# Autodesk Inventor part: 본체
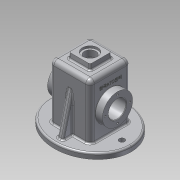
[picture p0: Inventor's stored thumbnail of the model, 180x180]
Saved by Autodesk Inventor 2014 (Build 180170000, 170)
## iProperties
Created: 2017-07
Part Number: 본체
Material: 알루미늄 6061
Document SubType Name: Modeling
Designer: user
Density: 2.71 g/cm^3
Appearance: 알루미늄 - 평지
Mass: 892.712 g
Surface Area: 987.354 cm^2
Volume: 329.414 cm^3
Author: user
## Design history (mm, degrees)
sketch "스케치1"
  geometry: 1 further point
sketch "스케치2"
  geometry: 1 further point
sketch "스케치3"
  geometry: 1 further point; 1 other entity
  constraints: 2 other
extrude "돌출1" new body sketch "스케치3" distance "d2" = 10; taper "d3" = 0 deg
sketch "스케치4"
  geometry: L1 (-37, -37)-(37, -37); L2 (37, -37)-(37, 37); L3 (37, 37)-(-37, 37); L4 (-37, 37)-(-37, -37); L5 (-37, -37)-(37, 37); L6 (37, -37)-(-37, 37); 1 further point; 1 other entity
  constraints: 12 end point, 2 midpoint, 2 parallel, 1 horizontal, 1 perpendicular, 1 other
  dimensions: "d4" = 74 distance of L3.end L2.end; "d5" = 74 distance of L2.end L1.end
extrude "돌출2" join sketch "스케치4" distance "d6" = 100; taper "d7" = 0 deg
fillet "모깎기1" dims "d8" = 8
fillet "모깎기2" dims "d9" = 8
sketch "스케치5"
  geometry: L1 (-32, -32)-(32, -32); L2 (32, -32)-(32, 32); L3 (32, 32)-(-32, 32); L4 (-32, 32)-(-32, -32); L5 (-32, -32)-(32, 32); L6 (32, -32)-(-32, 32); 1 further point; 1 other entity
  constraints: 12 end point, 2 midpoint, 2 parallel, 1 horizontal, 1 perpendicular, 1 other
  dimensions: "d10" = 64 distance of L3.end L2.end; "d11" = 64 distance of L2.end L1.end
extrude "돌출3" cut sketch "스케치5" distance "d12" = 105; taper "d13" = 0 deg
sketch "스케치6"
  geometry: L1 (-32, 0)-(32, 0) reference; L2 (-32, 0)-(-32, 105) reference; L3 (-32, 105)-(32, 105) reference; L4 (32, 0)-(32, 105) reference; L5 (75, 10)-(-75, 10) reference; L6 (-75, 0)-(75, 0) reference; L7 (-37, 102)-(-29, 102) reference; L8 (-37, 102)-(-37, 10) reference; L9 (-37, 10)-(-29, 10) reference; L10 (-29, 10)-(-29, 102) reference; L11 (-29, 110)-(-29, 102) reference; L12 (-29, 102)-(29, 102) reference; L13 (29, 102)-(29, 110) reference; L14 (29, 110)-(-29, 110) reference; L15 (29, 102)-(37, 102) reference; L16 (29, 102)-(29, 10) reference; L17 (29, 10)-(37, 10) reference; L18 (37, 10)-(37, 102) reference; L19 (-37, 10)-(-37, 55); L20 (-37, 82.5)-(-50, 82.5); L21 (-50, 82.5)-(-50, 71); L22 (-50, 71)-(-25, 71); L23 (-37, 82.5)-(-32, 82.5); L24 (-37, 55)-(-37, 71); L25 (-32, 82.5)-(-17, 82.5); L26 (-25, 71)-(-25, 75.5); L27 (-25, 75.5)-(-32, 82.5); L28 (-32, 0)-(-32, 105) reference; L29 (-37, 55)-(-17, 55); L30 (-37, 102)-(-37, 10) reference; L31 (-25, 71)-(-25, 75.5); L32 (-32, 82.5)-(-25, 75.5); L33 (-32, 82.5)-(-50, 82.5); L34 (-50, 82.5)-(-50, 71); L35 (-50, 71)-(-25, 71); 1 further point
  constraints: 30 end point, 6 perpendicular, 4 collinear, 4 point on line, 1 horizontal
  node "투영된 루프1"
  node "투영된 루프2"
  node "투영된 루프3"
  node "투영된 루프4"
  node "투영된 루프5"
revolve "회전1" stored, may be unused: angle "d22" = 90 deg
fillet "모깎기3" dims "d23" = 0.5
sketch "스케치7"
  geometry: C1 r 16 at (0, 0) reference; C2 r 16 at (0, 0) reference; 1 further point
extrude "돌출4" cut sketch "스케치7" distance "d24" = 20; taper "d25" = 0 deg
sketch "스케치8"
  geometry: L1 (0, 0)-(-22.5, 0); C1 r 27.5 at (0, 0) reference; 1 further point
  constraints: 2 end point, 1 horizontal
  dimensions: "d26" = 22.5 distance of L1.start L1.end
hole "구멍1" sketch "스케치8" at (-22.5, 0) diameter "d27" = 3.242; stored, may be unused: countersink angle "d31" = 90 deg, drill point angle "d33" = 118 deg; dims "d28" = 8, "d29" = 4, "d30" = 2, "d32" = 10
fillet "모깎기4" dims "d37" = 3
fillet "모깎기5" dims "d38" = 3
chamfer "모따기1" distance "d39" = 1; stored, may be unused: second distance "d40" = 2, angle "d41" = 45 deg
sketch "스케치9"
  geometry: C1 r 16 at (0, 0) reference; C2 r 16 at (0, 0) reference; 1 further point
extrude "돌출5" cut sketch "스케치9" distance "d42" = 20; taper "d43" = 0 deg
revolve "회전2" stored, may be unused: angle "d44" = 90 deg
sketch "스케치10"
  geometry: L1 (0, 0)-(-22.472, 0); C1 r 27.5 at (0, 0) reference; 1 further point
  constraints: 2 end point, 1 horizontal
hole "구멍2" sketch "스케치10" at (-22.472, 0) diameter "d46" = 3.242; stored, may be unused: countersink angle "d50" = 90 deg, drill point angle "d52" = 118 deg; dims "d47" = 8, "d48" = 4, "d49" = 2, "d51" = 10
fillet "모깎기6" dims "d56" = 0.5
fillet "모깎기7" dims "d57" = 0.5
fillet "모깎기8" dims "d58" = 3
fillet "모깎기9" dims "d59" = 3
sketch "스케치11"
  geometry: L1 (-20, -20)-(20, -20); L2 (20, -20)-(20, 20); L3 (20, 20)-(-20, 20); L4 (-20, 20)-(-20, -20); L5 (-20, -20)-(20, 20); L6 (20, -20)-(-20, 20); 1 further point
  constraints: 12 end point, 2 midpoint, 2 parallel, 1 horizontal, 1 perpendicular
  dimensions: "d60" = 40 distance of L3.end L2.end; "d61" = 40 distance of L2.end L1.end
extrude "돌출6" join sketch "스케치11" distance "d62" = 10; taper "d63" = -5 deg
fillet "모깎기10" dims "d64" = 3
fillet "모깎기11" dims "d65" = 3
sketch "스케치12"
  geometry: 1 further point
hole "구멍3" sketch "스케치12" at (0, 0) diameter "d66" = 21; stored, may be unused: countersink angle "d70" = 90 deg, drill point angle "d72" = 0 deg; dims "d67" = 8, "d68" = 28, "d69" = 4, "d71" = 20
sketch "스케치13"
  geometry: L1 (0, 0)-(58, 0); C1 r 5 at (58, 0); 1 other entity
  constraints: 2 end point, 1 centre point, 1 coincident, 1 horizontal, 1 other
  dimensions: "d73" = 58 distance of L1.start L1.end; "d74" = 10 diameter of C1
extrude "돌출7" cut sketch "스케치13" stored distance "d75" = 10; taper "d76" = 0 deg
fillet "모깎기12" dims "d77" = 3
sketch "스케치14"
  geometry: L1 (-37, 10)-(-37, 102) reference; L2 (-29, 102)-(-37, 102) reference; L3 (-29, 102)-(-29, 10) reference; L4 (-29, 10)-(-37, 10) reference; L5 (-37, 10)-(-37, 102) reference; L6 (29, 105)-(10.5, 105) reference; L7 (10.5, 105)-(10.5, 116) reference; L8 (10.5, 116)-(14, 116) reference; L9 (14, 116)-(14, 120) reference; L10 (14, 120)-(19.125, 120) reference; L11 (19.125, 120)-(19.76, 112.739) reference; L12 (22.749, 110)-(29, 110) reference; L13 (37, 102)-(37, 10) reference; L14 (37, 10)-(62, 10) reference; L15 (65, 7)-(65, 0) reference; L16 (65, 0)-(32, 0) reference; L17 (32, 0)-(32, 102) reference; L18 (-32, 102)-(-32, 0) reference; L19 (-32, 0)-(-65, 0) reference; L20 (-65, 0)-(-65, 7) reference; L21 (-62, 10)-(-37, 10) reference; L22 (-37, 10)-(-37, 102) reference; L23 (-29, 110)-(-22.749, 110) reference; L24 (-19.76, 112.739)-(-19.125, 120) reference; L25 (-19.125, 120)-(-14, 120) reference; L26 (-14, 120)-(-14, 116) reference; L27 (-14, 116)-(-10.5, 116) reference; L28 (-10.5, 116)-(-10.5, 105) reference; L29 (-10.5, 105)-(-29, 105) reference; L30 (-55, 10)-(-37, 82.194); L31 (-55, 10)-(-37, 10); L32 (-37, 10)-(-37, 82.194); L33 (-37, 82.194)-(-55, 10); A1 r 3 centre (29, 102) between (32, 102) and (29, 105) reference; A2 r 3 centre (22.749, 113) between (19.76, 112.739) and (22.749, 110) reference; A3 r 8 centre (29, 102) between (37, 102) and (29, 110) reference; A4 r 3 centre (-29, 102) between (-29, 105) and (-32, 102) reference; A5 r 8 centre (-29, 102) between (-29, 110) and (-37, 102) reference; A6 r 3 centre (-22.749, 113) between (-22.749, 110) and (-19.76, 112.739) reference; 1 further point
  constraints: 8 end point, 2 collinear, 2 point on line, 1 parallel, 1 vertical alignment, 2 other
  dimensions: "d79" = 14 deg angle of L20 L30
extrude "돌출8" join sketch "스케치14" stored distance "d80" = 10; taper "d81" = 0 deg
fillet "모깎기13" dims "d82" = 3
fillet "모깎기14" dims "d83" = 3
sketch "스케치15"
  geometry: L1 (0, 0)-(10, 0) reference; L2 (10, 92)-(10, 0) reference; L3 (10, 0)-(0, 0) reference; L4 (0, 0)-(0, 92) reference; L5 (0, 92)-(10, 92) reference; L6 (37, 0)-(37, 102) reference; L7 (37, 102)-(72.122, 102) reference; L8 (72.122, 102)-(72.122, 95) reference; L9 (68.631, 92)-(42, 92) reference; L10 (42, 92)-(42, 0) reference; L11 (34, -8)-(-24, -8) reference; L12 (-32, 0)-(-32, 92) reference; L13 (-32, 92)-(-58.631, 92) reference; L14 (-62.122, 95)-(-62.122, 102) reference; L15 (-62.122, 102)-(-27, 102) reference; L16 (-27, 102)-(-27, 0) reference; L17 (-24, -3)-(34, -3) reference; A1 r 3 centre (34, 0) between (34, -3) and (37, 0) reference; A2 r 8 centre (34, 0) between (34, -8) and (42, 0) reference; A3 r 8 centre (-24, 0) between (-32, 0) and (-24, -8) reference; A4 r 3 centre (-24, 0) between (-27, 0) and (-24, -3) reference; 1 further point
  constraints: 2 other
extrude "돌출9" cut sketch "스케치15" stored distance "d84" = 10; taper "d85" = 0 deg
fillet "모깎기15" dims "d86" = 3
fillet "모깎기16" dims "d87" = 3
fillet "모깎기17" dims "d88" = 3
chamfer "모따기2" distance "d89" = 1; stored, may be unused: second distance "d90" = 2, angle "d91" = 45 deg
node "작업 평면1"
sketch "스케치16"
  geometry: L1 (89, 66)-(0, 66) reference; L2 (-18, 45.137)-(-18, 12.863) reference; 2 further points
  constraints: 1 other
  dimensions: "d93" = 37 distance from line of L1 point (12, 29); "d94" = 30 distance from line of L2 point (12, 29)
feature "엠보싱1" sketch "스케치16" dims "d95" = 0.5, "d96" = 0
sketch "스케치17"
  geometry: L1 (0, 0)-(10, 0) reference; L2 (0, 0)-(0, -92) reference; L3 (0, -92)-(10, -92) reference; L4 (10, -92)-(10, 0) reference; 1 further point
extrude "돌출10" cut sketch "스케치17" stored distance "d97" = 10; taper "d98" = 0 deg
node "솔리드1"
pattern_circular "원형 패턴1" dims angle "d35" = 360 deg
mirror "대칭1"
pattern_circular "원형 패턴2" dims angle "d54" = 360 deg
mirror "대칭2"
mirror "대칭3"
node "투영된 루프6"
node "투영된 루프7"
node "투영된 루프8"
node "절단 모서리 투영1"
node "절단 모서리 투영2"
other parameters: "d92" = 7
